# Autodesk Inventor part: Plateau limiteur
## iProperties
Created: 2002-05
Part Number: Plateau limiteur
Material: Par défaut
Document SubType Name: Modélisation
Designer: Flavien MARTY
Control State: 0
Master: False
Checked Out: False
Shininess: 20.0
Length Units: 11269
Angle Units: 11279
Time Units: 11290
Mass Units: 11283
Length Display Precision: 3
Angle Display Precision: 2
Compacted: True
Density: 0.0
Volumn: 0.0
Area: 0.0
PropertySet Name: Model Information
Author: Flavien MARTY
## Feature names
1. Extrusion1
2. Extrusion2
3. Extrusion3
4. Perçage1 [Hole]
